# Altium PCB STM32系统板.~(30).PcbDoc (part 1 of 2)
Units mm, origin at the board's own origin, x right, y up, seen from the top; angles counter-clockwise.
Board outline 191.7 x 146.7 mm, 4 copper layers (TopLayer, MidLayer1, MidLayer2, BottomLayer); 154 components, 101 nets, 554 pads, 177 vias.
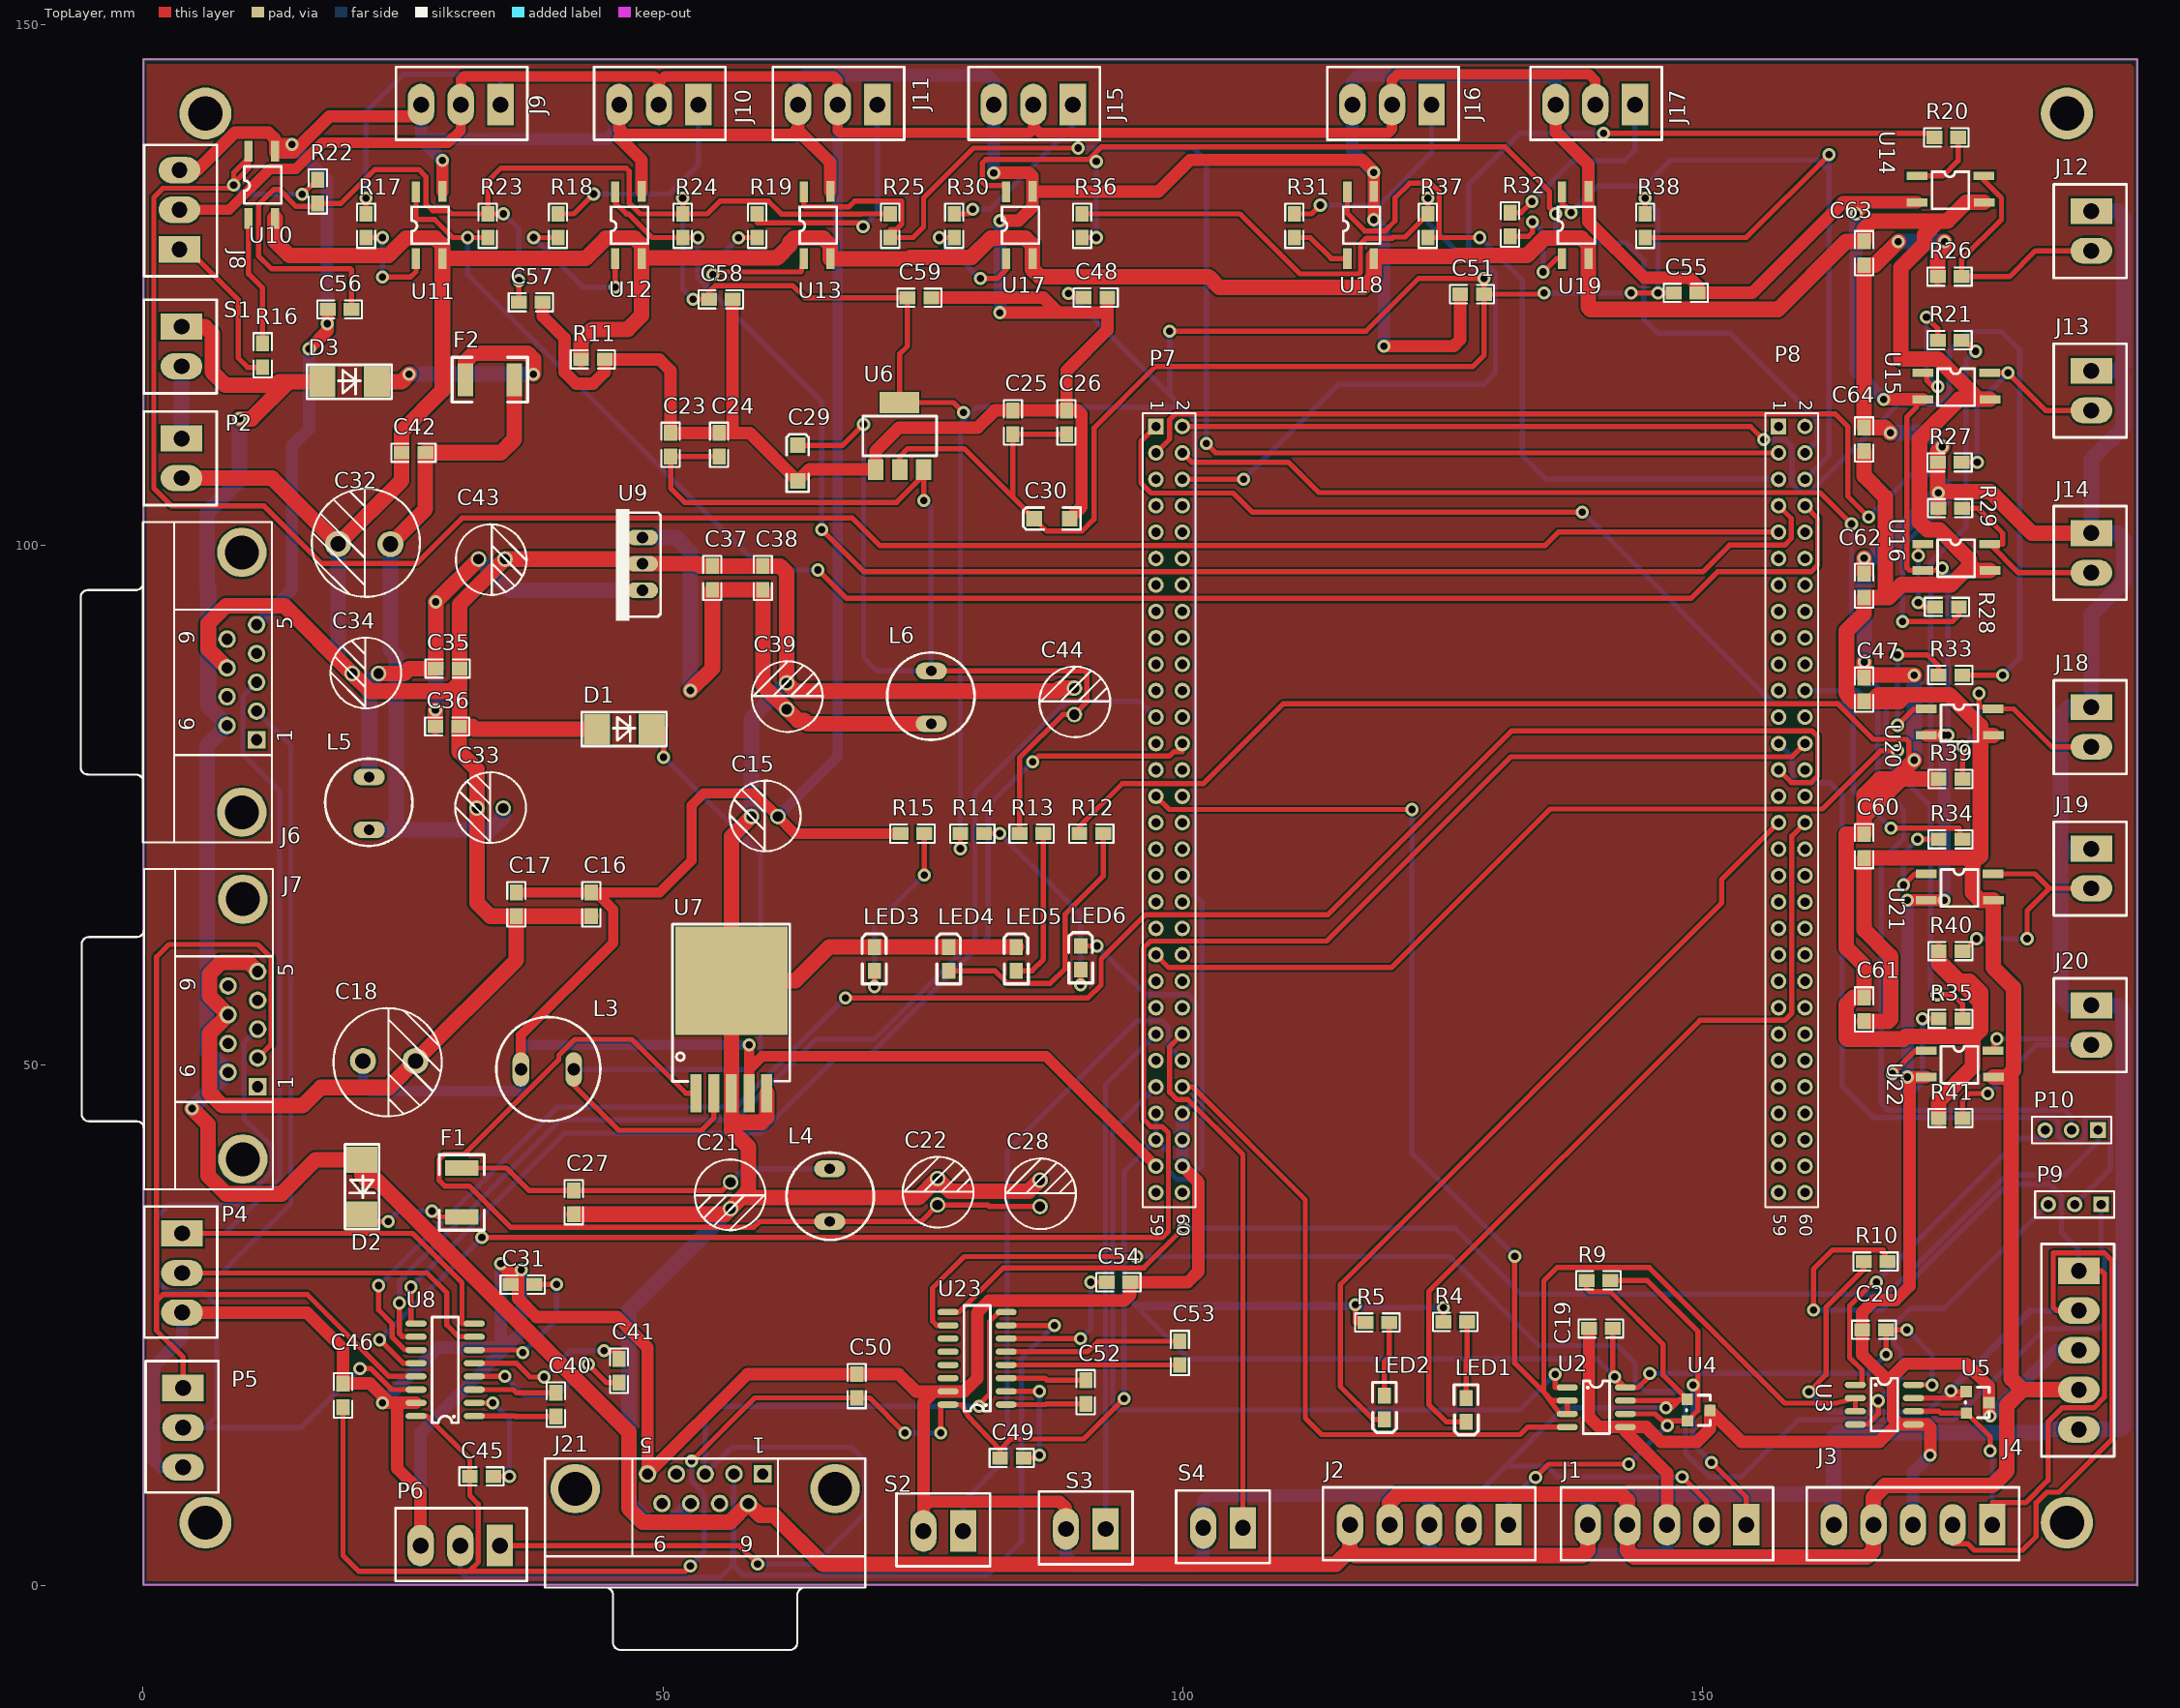
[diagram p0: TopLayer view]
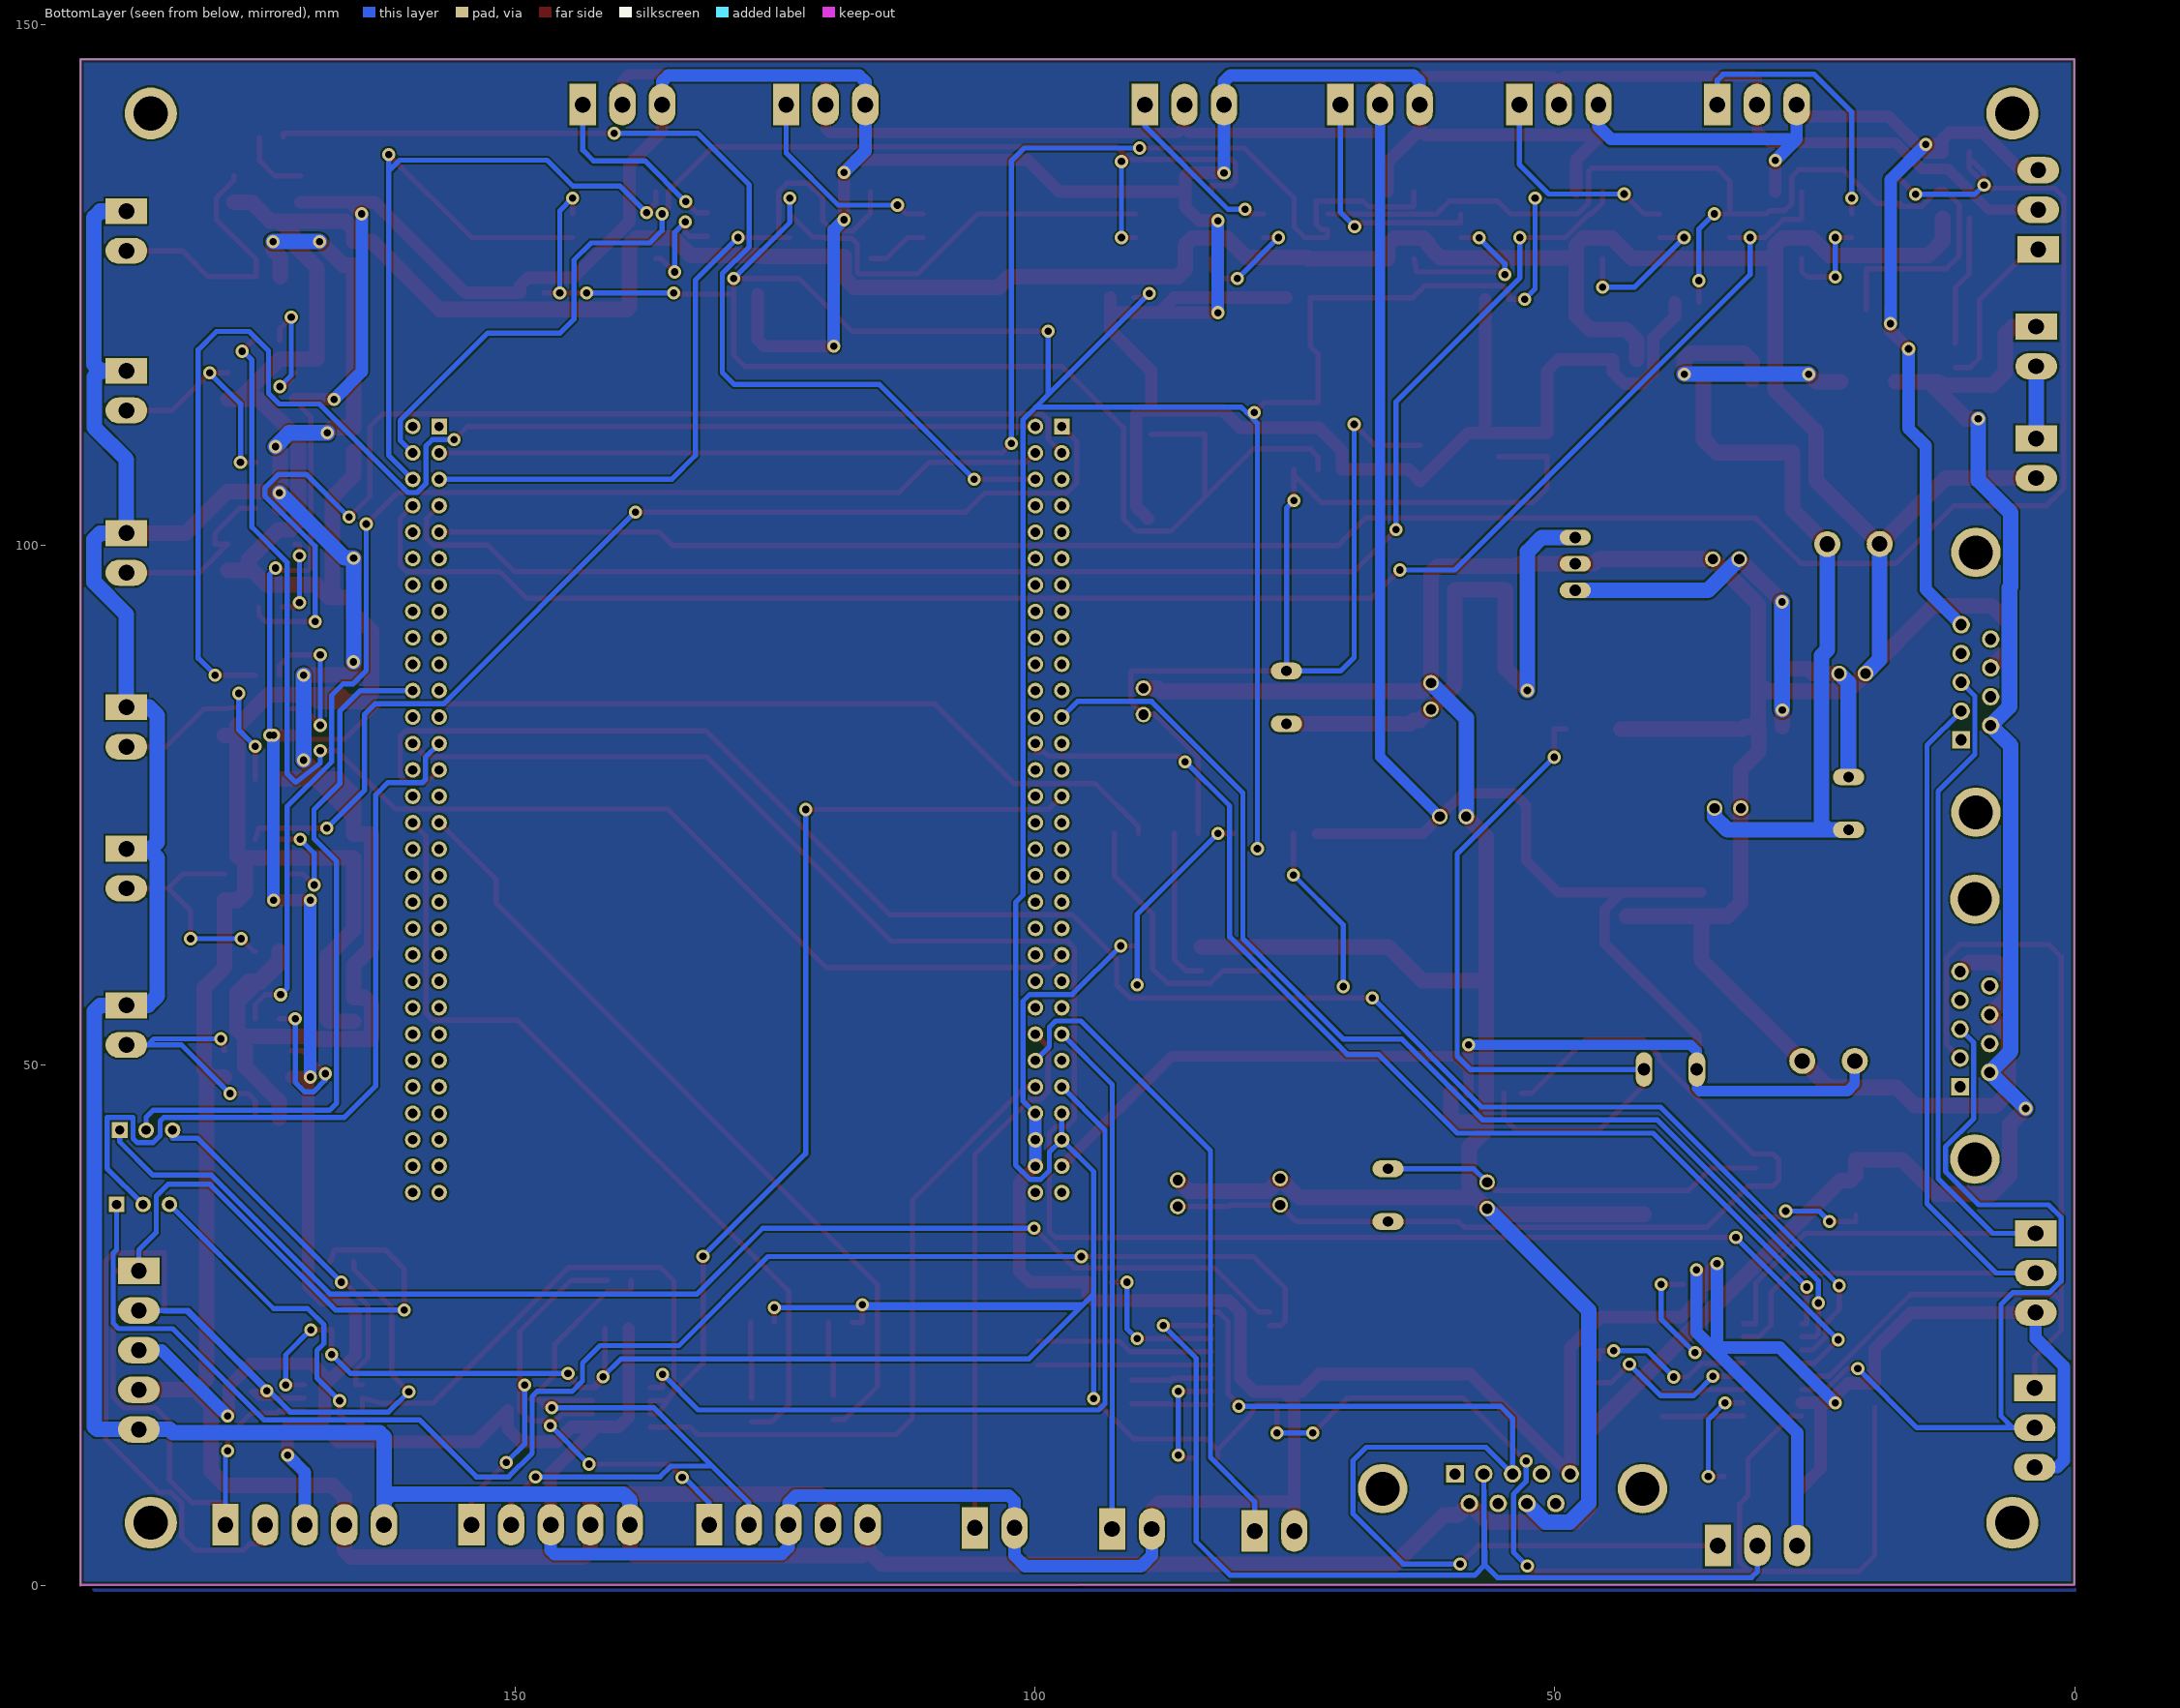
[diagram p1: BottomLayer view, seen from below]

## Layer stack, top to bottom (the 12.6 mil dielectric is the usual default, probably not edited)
TopSolder: solder mask 0.0102, Solder Resist, Dk 3.5
TopLayer: signal copper 0.0356
Dielectric1: dielectric 0.32, FR-4, Dk 4.8
MidLayer1: signal copper 0.0356
Dielectric2: dielectric 0.32, FR-4, Dk 4.8
MidLayer2: signal copper 0.0356
Dielectric3: dielectric 0.32, FR-4, Dk 4.8
BottomLayer: signal copper 0.0356
BottomSolder: solder mask 0.0102, Solder Resist, Dk 3.5

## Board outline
0.05,0.05 0.05,146.7 191.75,146.7 191.75,0

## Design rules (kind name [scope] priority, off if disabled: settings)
Clearance [All] p1: gap=0.2 ignorepadtopadclearanceinfootprint=FALSE except(0: Arc-Hole Track-Hole SMDPad-Hole THPad-Hole Via-Hole Fill-Hole Poly-Hole Region-Hole Text-Hole)
FabricationTestPointUsage TestPointUsage [All] p1: valid=0 allowmultiple=FALSE
FabricationTestpoint Testpoint [All] p1: side=3 testpointundercomponent=TRUE minsize=1.016 maxsize=2.54 preferedsize=1.524 minholesize=0.508 maxholesize=1.016 preferedholesize=0.813 testpointgrid=0.025 allowsidetop=TRUE allowsidebottom=TRUE usegrid=TRUE gridtolerance=0
HoleSize [All] p1: absolutevalues=TRUE maxlimit=5.5 minlimit=0.025 maxpercent=80.000 minpercent=20.000
PlaneConnect [All] p1: planeconnectstyle=Relief reliefexpansion=1 reliefentries=4 reliefconductorwidth=2 reliefairgap=0.254
PolygonConnect [All] p1: connectstyle=Relief reliefconductorwidth=0.3 reliefentries=4 polygonreliefangle="90 Angle" airgapwidth=0.254
RoutingCorners [All] p1: cornerstyle=45-Degree minsetback=0.025 maxsetback=4
RoutingLayers [All] p1: top layer_v5=TRUE mid layer 1_v5=FALSE mid layer 2_v5=FALSE bottom layer_v5=TRUE
RoutingVias [All] p1: holewidth=0.711 width=1.27 viastyle="Through Hole" minholewidth=0.711 minwidth=1.27 maxholewidth=0.711 maxwidth=1.27
SilkToSolderMaskClearance SilkscreenOverComponentPads [IsPad] p1: minsilkscreentomaskgap=0.254 clearancetoexposedcopper=TRUE
SolderMaskExpansion [All] p1: expansion=0.2
Width [All] p1: maxlimit=10 minlimit=0.254 preferedwidth=0.5 midlayer1_maxwidth=0.762 midlayer1_prefwidth=0.381 midlayer2_maxwidth=0.762 midlayer2_prefwidth=0.381 minimp=50.000000 maximp=50.000000 favimp=50.000000
23 further rules are at their usual default settings.

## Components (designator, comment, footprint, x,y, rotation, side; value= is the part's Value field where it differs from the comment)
C15 "100uf/16V" C6.5-35V47uf 61.05,73.9 r180 top
C16 "10nf/50V 5%" 0805C 43.082,66.55 r270 top
C17 "100nf/50V 5%" 0805C 35.882,66.55 r270 top
C18 "470u/16V" C10-35V330uf 21.15,50.4 r0 top
C19 "100nf/50V 5%" 0805C 139.1,24.65 r0 top
C20 "100nf/50V 5%" 0805C 165.362,24.532 r0 top
C21 "10uf/35V" C6.5-35V47uf 56.5,38.741 r270 top
C22 "220uf/35V" C6.5-35V47uf 76.4,36.551 r90 top
C23 "100nf/50V 5%" 0805C 50.75,108.55 r90 top
C24 "10nf/50V 5%" 0805C 55.418,108.55 r90 top
C25 "100nf/50V 5%" 0805C 83.668,110.7 r90 top
C26 "10nf/50V 5%" 0805C 88.818,110.7 r90 top
C27 "100nf/50V 5%" 0805C 41.4,37.9 r270 top
C28 "10u/35V" C6.5-35V47uf 86.25,36.401 r90 top
C29 "16V10uf" 1206-2 62.95,107.885 r90 top
C30 "16V10uf" 1206-2 87.4,102.55 r180 top
C31 "100nf/50V 5%" 0805C 37.588,28.918 r180 top
C32 "220uf/35V" C10-35V330uf 23.794,100.091 r180 top
C33 "10uf/35V" C6.5-35V47uf 34.64,74.7 r180 top
C34 "220uf/35V" C6.5-35V47uf 22.65,87.65 r180 top
C35 "100nf/50V 5%" 0805C 28.2,88.1 r0 top
C36 "10nf/50V 5%" 0805C 28.162,82.532 r0 top
C37 "10nf/50V 5%" 0805C 54.768,95.75 r90 top
C38 "100nf/50V 5%" 0805C 59.618,95.75 r90 top
C39 "47uf 50V" C6.5-35V47uf 61.9,84.21 r90 top
C40 "100nf/50V 5%" 0805C 39.718,16.262 r90 top
C41 "100nf/50V 5%" 0805C 45.75,21.7 r270 top
C42 "100nf/50V 5%" 0805C 27.1,108.9 r180 top
C43 "47uf 50V" C6.5-35V47uf 32.26,98.65 r0 top
C44 "10uf 50V" C6.5-35V47uf 89.55,83.7 r90 top
C45 "100nf/50V 5%" 0805C 31.462,10.432 r0 top
C46 "10uf/50V 5%" 0805C 19.25,17.15 r90 top
C47 "100nf/50V 5%" 0805C 165.518,85.012 r90 top
C48 "100nf/50V 5%" 0805C 92.688,123.818 r180 top
C49 "100nf/50V 5%" 0805C 82.45,12.2 r0 top
C50 "10uf/50V 5%" 0805C 68.65,18.05 r90 top
C51 "100nf/50V 5%" 0805C 126.7,124.1 r0 top
C52 "100nf/50V 5%" 0805C 90.668,17.457 r90 top
C53 "100nf/50V 5%" 0805C 99.682,23.402 r270 top
C54 "100nf/50V 5%" 0805C 92.7,29.1 r0 top
C55 "100nf/50V 5%" 0805C 149.438,124.268 r180 top
C56 "100nf/50V 5%" 0805C 17.812,122.632 r0 top
C57 "100nf/50V 5%" 0805C 38.388,123.368 r180 top
C58 "100nf/50V 5%" 0805C 56.65,123.65 r180 top
C59 "100nf/50V 5%" 0805C 75.75,123.8 r180 top
C60 "100nf/50V 5%" 0805C 165.518,69.962 r90 top
C61 "100nf/50V 5%" 0805C 165.518,54.262 r90 top
C62 "100nf/50V 5%" 0805C 165.518,95.002 r90 top
C63 "100nf/50V 5%" 0805C 165.472,129.152 r270 top
C64 "100nf/50V 5%" 0805C 165.518,109.062 r90 top
D1 "1N5822" SS34 48.4,82.75 r90 top
D2 "1N5822" SS34 21.49,36.157 r0 top
D3 "1N5822" SS34 21.984,116.14 r90 top
F1 "500mA" 1812 30.65,37.751 r90 top
F2 "500mA" 1812 33.35,115.9 r0 top
J1 "Header 5" CON-5P-3.81 154.119,5.8 r180 top
J2 "Header 5" CON-5P-3.81 131.249,5.8 r180 top
J3 "Header 5" CON-5P-3.81 177.769,5.8 r180 top
J4 "Header 5" CON-5P-3.81 186.15,30.159 r270 top
J6 "母头" DSUB1.385-2H9 0,86.805 r90 top
J7 "公头" DSUB1.385-2H9 0.1,53.455 r90 top
J8 "CON3" CON-3P-3.81 3.525,128.455 r90 top
J9 "CON3" CON-3P-3.81 34.335,142.375 r180 top
J10 "CON3" CON-3P-3.81 53.385,142.375 r180 top
J11 "CON3" CON-3P-3.81 70.585,142.375 r180 top
J12 "红色" CON-2P-3.81 187.35,132.1 r270 top
J13 "红色" CON-2P-3.81 187.35,116.75 r270 top
J14 "红色" CON-2P-3.81 187.35,101.15 r270 top
J15 "CON3" CON-3P-3.81 89.395,142.375 r180 top
J16 "CON3" CON-3P-3.81 123.885,142.375 r180 top
J17 "CON3" CON-3P-3.81 143.435,142.375 r180 top
J18 "红色" CON-2P-3.81 187.35,84.41 r270 top
J19 "红色" CON-2P-3.81 187.35,70.8 r270 top
J20 "红色" CON-2P-3.81 187.35,55.75 r270 top
J21 "母头" DSUB1.385-2H9 54.055,-0.23 r180 top
L3 "331" LC-10 38.45,49.85 r0 top
L4 "Inductor" LC-8.2 66.05,40.001 r270 top value="10uH 2A"
L5 "Inductor" LC-8.2 21.733,72.654 r90 top value="10uH 2A"
L6 "10uH 2A" LC-8.2 75.783,82.854 r90 top
LED1 "LED R" 0805D 127.2,17.916 r270 top
LED2 "LED B" 0805D 119.35,18.15 r270 top
LED3 "LED G" 0805D 70.35,59.15 r90 top
LED4 "LED B" 0805D 77.5,59.15 r90 top
LED5 "LED R" 0805D 84,59.15 r90 top
LED6 "LED B" 0805D 90.2,59.25 r90 top
P2 "Power_24V" CON-2P-3.81 3.7,110.25 r270 top
P4 "RS232_2" CON-3P-3.81 3.725,33.795 r270 top
P5 "RS232_4" CON-3P-3.81 3.825,18.925 r270 top
P6 "RS232_1" CON-3P-3.81 34.285,3.825 r180 top
P7 "Header 30X2" HDR2X30 97.4,111.4 r270 top
P8 "Header 30X2" HDR2X30 157.276,111.4 r270 top
P9 "TX5" HDR1X3 188.29,36.6 r180 top
P10 "RX5" HDR1X3 187.99,43.75 r180 top
R4 "10K 1%" 0805R 127.3,25.35 r180 top
R5 "10K 1%" 0805R 119.813,25.293 r180 top
R9 "120R 1%" 0805R 138.837,29.257 r0 top
R10 "120R 1%" 0805R 165.487,31.057 r0 top
R11 "0R 1%" 0805R 42.137,117.807 r0 top
R12 "47K 1%" 0805R 92.302,72.302 r180 top
R13 "10k 1%" 0805R 86.552,72.302 r180 top
R14 "10K 1%" 0805R 80.852,72.302 r180 top
R15 "10K 1%" 0805R 75.102,72.302 r180 top
R16 "620R 1%" 0805R 11.457,119.363 r270 top
R17 "620R 1%" 0805R 21.493,129.587 r90 top
R18 "620R 1%" 0805R 39.95,129.587 r90 top
R19 "620R 1%" 0805R 59.1,129.587 r90 top
R20 "620R 1%" 0805R 174.513,139.243 r180 top
R21 "620R 1%" 0805R 172.6,119.65 r0 top
R22 "2K 1%" 0805R 16.757,135.113 r270 top
R23 "2K 1%" 0805R 33.193,129.587 r90 top
R24 "2K 1%" 0805R 51.943,129.587 r90 top
R25 "2K 1%" 0805R 71.893,129.587 r90 top
R26 "2K 1%" 0805R 172.6,125.764 r0 top
R27 "2K 1%" 0805R 172.6,107.9 r0 top
R28 "620R 1%" 0805R 172.35,94 r0 top
R29 "2K 1%" 0805R 172.65,103.5 r0 top
R30 "620R 1%" 0805R 78.05,129.587 r90 top
R31 "620R 1%" 0805R 110.75,129.587 r90 top
R32 "620R 1%" 0805R 131.493,129.705 r90 top
R33 "620R 1%" 0805R 172.673,87.457 r0 top
R34 "620R 1%" 0805R 172.687,71.657 r0 top
R35 "620R 1%" 0805R 172.687,54.4 r0 top
R36 "2K 1%" 0805R 90.343,129.587 r90 top
R37 "2K 1%" 0805R 123.593,129.587 r90 top
R38 "2K 1%" 0805R 144.493,129.587 r90 top
R39 "2K 1%" 0805R 172.687,77.457 r0 top
R40 "2K 1%" 0805R 172.687,60.907 r0 top
R41 "2K 1%" 0805R 172.687,44.857 r0 top
S1 "SW POWER" CON-2P-3.81 3.7,121 r270 top
S2 "KEY-9" CON-2P-3.81 78.86,5.2 r180 top
S3 "KEY-9" CON-2P-3.81 92.56,5.4 r180 top
S4 "KEY-9" CON-2P-3.81 105.76,5.5 r180 top
U2 "SP3485" SO-8 139.75,17.1 r0 top
U3 "SP3485" SO-8 167.45,17.35 r0 top
U4 "SM712" SM712 147.757,18.918 r270 top
U5 "SM712" SM712 174.577,19.668 r270 top
U6 "LM1117-3.3" SOT-223 73.123,110.226 r0 top
U7 "LM2596-5" TO-263-5 56.6,57.65 r0 top
U8 "MAX3232" SO-16 29.05,20.7 r180 top
U9 "ZLG K7805-500" TO-220 48.05,99 r90 top
U10 "TLP181" TLP-181 10.15,131.42 r90 top
U11 "TLP181" TLP-181 26.25,127.548 r90 top
U12 "TLP181" TLP-181 45.41,127.548 r90 top
U13 "TLP181" TLP-181 63.55,127.548 r90 top
U14 "TLP181" TLP-181 170.6,135.49 r0 top
U15 "TLP181" TLP-181 171.15,116.55 r0 top
U16 "TLP181" TLP-181 171.15,100.1 r0 top
U17 "TLP181" TLP-181 83,127.548 r90 top
U18 "TLP181" TLP-181 115.81,127.548 r90 top
U19 "TLP181" TLP-181 136.45,127.548 r90 top
U20 "TLP181" TLP-181 171.474,84.25 r0 top
U21 "TLP181" TLP-181 171.474,68.39 r0 top
U22 "TLP181" TLP-181 171.474,51.39 r0 top
U23 "MAX3232" SO-16 80.2,21.8 r180 top

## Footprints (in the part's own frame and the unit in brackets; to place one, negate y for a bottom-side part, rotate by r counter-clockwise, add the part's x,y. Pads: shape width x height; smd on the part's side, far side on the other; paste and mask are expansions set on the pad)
0805C [mil]
  rect 60x50 smd: 1(-1.89,0.71) 2(88.11,0.71)
  silkscreen extent -41,-34 127,35
0805D [mil]
  rect 60x50 smd: 1(-3.11,0.95) 2(86.89,0.95)
  silkscreen extent -53,-44 137,47
0805R [mil]
  rect 60x50 smd: 1(-0.91,1.69) 2(89.09,1.69)
  silkscreen extent -40,-33 128,36
1206-2 [mm]
  rect 1.5x1.5 smd: 1(1.715,0) 2(-1.714,0)
  silkscreen extent -2.76,-1.05 2.76,1.05
1812 [mil]
  rect 60x125 smd: 1(-92.5,0) 2(92.5,0)
  silkscreen extent -143,-85 142,85
C6.5-35V47uf [mm]
  round 1.5 hole 1: 1(0,0) 2(2.54,0)
  silkscreen extent -2.18,-3.45 4.62,3.35
C10-35V330uf [mm]
  round 2.5 hole 1.5: 1(0,0) 2(5.044,-0.009)
  silkscreen extent -2.83,-5.33 7.57,5.07
CON-2P-3.81 [mm]
  rect 2.5x4 hole 1.524: 1(0,0)
  oval 2.5x4 hole 1.524: 2(3.81,0)
  silkscreen extent -2.59,-3.61 6.41,3.39
CON-3P-3.81 [mil]
  rect 100x157.48 hole 60: 1(-1,1)
  oval 100x157.48 hole 60: 2(149,1) 3(299,1)
  silkscreen extent -103,-141 394,135
CON-5P-3.81 [mm]
  rect 2.54x4 hole 1.524: 1(-0.051,0)
  oval 2.54x4 hole 1.524: 2(3.759,0) 3(7.569,0) 4(11.379,0) 5(15.189,0)
  silkscreen extent -2.64,-3.61 17.78,3.39
DSUB1.385-2H9 [mm] "Connector; D Subminiature; 9 Position; Right Angle; Pitch 1.385 mm"
  rect 1.69x1.69 hole 1.09: 1(-5.54,-10.92)
  round 1.69 hole 1.09: 2(-2.77,-10.92) 3(0,-10.92) 4(2.77,-10.92) 5(5.54,-10.92) 6(-4.155,-8.08) 7(-1.385,-8.08) 8(1.385,-8.08) 9(4.155,-8.08)
  round 4.76 hole 3.26: 10(-12.495,-9.5) 11(12.495,-9.5)
  silkscreen extent -15.4,-12.4 15.4,6
HDR1X3 [mm] "Connector; Header; 3 Position"
  rect 1.5x1.5 hole 0.9: 1(0,0)
  round 1.5 hole 0.9: 2(2.54,0) 3(5.08,0)
  silkscreen extent -1.27,-1.27 6.35,1.27
HDR2X30 [mm] "Connector; Header; 30x2 Position"
  rect 1.5x1.5 hole 0.9: 1(0,0)
  round 1.5 hole 0.9: 2(0,2.54) 3(2.54,0) 4(2.54,2.54) 5(5.08,0) 6(5.08,2.54) 7(7.62,0) 8(7.62,2.54) 9(10.16,0) 10(10.16,2.54) 11(12.7,0) 12(12.7,2.54) 13(15.24,0) 14(15.24,2.54) 15(17.78,0) 16(17.78,2.54) 17(20.32,0) 18(20.32,2.54) 19(22.86,0) 20(22.86,2.54) 21(25.4,0) 22(25.4,2.54) 23(27.94,0) 24(27.94,2.54) 25(30.48,0) 26(30.48,2.54) 27(33.02,0) 28(33.02,2.54) 29(35.56,0) 30(35.56,2.54) 31(38.1,0) 32(38.1,2.54) 33(40.64,0) 34(40.64,2.54) 35(43.18,0) 36(43.18,2.54) 37(45.72,0) 38(45.72,2.54) 39(48.26,0) 40(48.26,2.54) 41(50.8,0) 42(50.8,2.54) 43(53.34,0) 44(53.34,2.54) 45(55.88,0) 46(55.88,2.54) 47(58.42,0) 48(58.42,2.54) 49(60.96,0) 50(60.96,2.54) 51(63.5,0) 52(63.5,2.54) 53(66.04,0) 54(66.04,2.54) 55(68.58,0) 56(68.58,2.54) 57(71.12,0) 58(71.12,2.54) 59(73.66,0) 60(73.66,2.54)
  silkscreen extent -1.27,-1.27 75.06,3.81
LC-8.2 [mm]
  oval 1.6x3 hole 1: 1(-0.034,-0.017) 2(5.046,-0.017)
  silkscreen extent -1.58,-4.17 6.81,4.23
LC-10 [mm]
  oval 1.6x3.3 hole 1.2: 1(-2.117,-0.271) 2(2.963,-0.271)
  silkscreen extent -4.47,-5.23 5.53,4.77
SM712 [mm]
  rect 1.1x1.1 smd: 1(1.068,0.743) 2(3.128,0.763) 3(2.118,2.923)
  silkscreen extent 0.65,0.66 3.57,2.95
SO-8 [mil]
  oval 80x24 smd: 1(-110,75) 2(-110,25) 3(-110,-25) 4(-110,-75) 5(110,-75) 6(110,-25) 7(110,25) 8(110,75)
  silkscreen extent -50,-100 50,100
SO-16 [mil]
  oval 80x24 smd: 1(-110,175) 2(-110,125) 3(-110,75) 4(-110,25) 5(-110,-25) 6(-110,-75) 7(-110,-125) 8(-110,-175) 9(110,-175) 10(110,-125) 11(110,-75) 12(110,-25) 13(110,25) 14(110,75) 15(110,125) 16(110,175)
  silkscreen extent -50,-200 50,200
SOT-223 [mil]
  rect 59x79 smd: 1(-104.55,-116.77) 2(-14,-116.77) 3(76.55,-116.77)
  rect 150x79 smd: 2(-14.67,136.77)
  silkscreen extent -154,-65 126,85
SS34 [mm]
  rect 3x2.5 smd: 1(-0.44,4.743) 2(-0.44,-0.517)
  silkscreen extent -2.08,-1.93 1.19,6.22
TLP-181 [mm]
  rect 2x0.8 smd: 1(0,0) 2(0,-2.54) 3(6.452,-2.54) 4(6.426,0)
  silkscreen extent 1.42,-3.15 4.98,0.41
TO-220 [mm]
  oval 1.5x3 hole 1.1: 1(-3.35,0.025) 2(-0.805,0.029) 3(1.735,0.029)
  silkscreen extent -6.27,-1.72 4.45,2.6
TO-263-5 [mm]
  rect 1.07x3.66 smd: 1(-3.425,-10.36) 2(-1.725,-10.36) 3(-0.025,-10.36) 4(1.675,-10.36) 5(3.375,-10.36)
  rect 10.8x10.41 smd: 3(-0.025,0.465)
  silkscreen extent -5.68,-9.21 5.6,5.89

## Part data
C15 C18 C21 C22 C28 C32 C33 C34 C39 C43 C44: library part "CAPACITOR POL", "Capacitor"
C16 C17 C19 C20 C23 C24 C25 C26 C27 C31 C35 C36 C37 C38 C40 C41 C42 C45 C46 C47 C48 C49 C50 C51 C52 C53 C54 C55 C56 C57 C58 C59 C60 C61 C62 C63 C64: library part CAP, "Capacitor"
C29 C30: library part CAP+
D1 D2 D3: library part DIODE, "Diode"
F1 F2: library part "Fuse 1", "Fuse"
J1 J2 J3 J4: "Header, 5-Pin"
J6 J7 J21: library part "D Connector 9", "Receptacle Assembly, 9 Position, Right Angle", PackageDocument=O
J8 J9 J10 J11 J15 J16 J17: "Connector"
J12 J13 J14 J18 J19 J20 P2: library part CON2, "Connector"
L3: library part INDUCTOR
L6: library part INDUCTOR1
LED1 LED2 LED3 LED4 LED5 LED6: library part LED
P4 P5 P6 P9 P10: library part "Header 3", "Header, 3-Pin"
P7 P8: "Header, 30-Pin, Dual row"
R4 R5 R9 R10 R11 R12 R13 R14 R15 R16 R17 R18 R19 R20 R21 R22 R23 R24 R25 R26 R27 R28 R29 R30 R31 R32 R33 R34 R35 R36 R37 R38 R39 R40 R41: library part RES2
S1: library part "SW SPST"
S2 S3 S4: library part KEY-2
U2 U3: library part MAX485
U6: library part LM1117
U7: library part LM2596-5.0
U9: library part VOLTREG
U10 U11 U12 U13 U14 U15 U16 U17 U18 U19 U20 U21 U22: library part TLP521-1

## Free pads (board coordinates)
  round 5 hole 3.3: 23(185,141.5) 24(6,141.5) 25(6,6) 26(185,6)

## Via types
v1: diameter 1.27, hole 0.711, TopLayer to BottomLayer, 177 vias

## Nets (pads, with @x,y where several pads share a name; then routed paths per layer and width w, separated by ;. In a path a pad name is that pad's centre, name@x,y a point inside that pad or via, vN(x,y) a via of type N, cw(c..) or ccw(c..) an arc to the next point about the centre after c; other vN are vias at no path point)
3V3: C19.2 C20.2 C25.1 C26.1 C30.1 C45.1 C46.1 C48.2 C49.1 C50.1 C51.2 C55.2 C56.2 C57.2 C58.2 C59.2 P7.53 P7.55 R4.2 R5.2 R14.2 R22.2 R23.2 R24.2 R25.2 R36.2 R37.2 R38.2 U2.8 U3.8 U6.2 U8.16 U23.16 | length 841.1
  TopLayer w0.5: C46.1@19.232,17.102 19.232,2.835 20.725,1.341 31.368,1.341 ; C56.2@20.05,122.65 20.05,126.462 19.948,126.563 12.343,126.563 11.099,127.808 11.099,132.71 12.597,134.209 13.08,134.209 14.731,132.558 16.8,132.558 R22.2@16.8,132.85 19.024,132.85 22.287,136.114 26.517,136.114 27.202,135.428 27.202,132.812 27.863,132.151 29.347,132.151 29.648,131.85 R23.2@33.15,131.85 ; U8.16@26.256,16.255 27.304,16.255 31.414,12.145 C45.1@31.414,10.45 31.414,8.606 32.232,7.788 32.232,2.205 31.368,1.341 ; v1(34.667,131.85) R23.2@33.15,131.85 ; C57.2@36.15,123.35 v1(36.15,125.421) ; v1(51.891,133.371) 51.9,133.362 R24.2@51.9,131.85 ; v1(52.628,1.824) 52.145,1.341 31.368,1.341 ; v1(52.755,11.933) 58.824,18.002 C50.1@68.632,18.002 69.874,18.002 v1(73.251,14.626) ; v1(52.888,123.632) C58.2@54.412,123.632 54.412,124.309 55.023,124.92 62.501,124.92 63.639,123.782 C59.2@73.512,123.782 73.512,119.121 72.75,118.359 U6.2@72.75,113.7 77.937,113.7 v1(78.891,112.746) ; R25.2@71.85,131.85 69.025,131.85 69.011,131.835 61.377,131.835 60.146,133.066 55.469,133.066 54.253,131.85 R24.2@51.9,131.85 ; U6.2@72.767,107.26 72.767,108.504 73.529,109.266 78.969,109.266 83.65,104.585 ; v1(76.707,14.626) 76.707,17.355 U23.16@77.406,17.355 78.702,17.355 79.304,16.291 82.402,13 ; v1(78.589,70.81) R14.2@78.589,72.259 ; C49.1@82.402,12.218 82.402,13 ; C26.1@88.8,110.652 C25.1@83.65,110.652 83.65,104.585 ; v1(88.975,124.201) 89.376,123.8 C48.2@90.45,123.8 ; R36.2@90.3,131.85 105.482,131.85 111.251,126.081 116.915,126.081 117.068,126.233 117.068,128.951 117.619,129.503 120.135,129.503 120.135,129.611 121.36,129.611 123.55,131.801 R37.2@123.55,131.85 v1(123.55,133.371) ; v1(94.335,17.928) 90.454,14.047 83.449,14.047 82.402,13 ; v1(98.729,120.569) 117.601,120.569 122.674,125.642 v1(128.938,125.642) C51.2@128.938,124.118 ; v1(116.585,26.945) 116.585,25.25 R5.2@117.55,25.25 ; R4.2@125.037,25.307 v1(125.037,26.665) ; v1(134.721,124.252) 134.587,124.118 C51.2@128.938,124.118 ; C19.2@141.338,24.668 141.338,19.892 142.225,19.005 U2.8@142.544,19.005 ; v1(141.513,20.036) U2.8@142.544,19.005 ; v1(143.103,124.252) 143.105,124.25 v1(145.676,124.25) C55.2@147.2,124.25 ; v1(144.449,133.371) v1(144.449,133.371) R38.2@144.45,131.85 ; v1(144.881,20.341) 144.881,20.112 143.774,19.005 U2.8@142.544,19.005 ; v1(167.6,22.156) C20.2@167.6,24.55 v1(169.62,24.55) ; U3.8@170.244,19.255 172.027,19.255 v1(172.033,19.248) ; R23.2@33.15,131.85 33.15,134.975 34.416,136.241 46.456,136.241 46.76,135.936 46.76,132.888 47.798,131.85 R24.2@51.9,131.85 ; 83.65,104.585 C30.1@85.685,102.55 86.885,101.35 90.314,101.35 91.439,102.474 91.439,111.25 97.367,117.178 127.888,117.178 128.938,118.228 C51.2@128.938,124.118
  BottomLayer w0.5: v1(34.667,131.85) 36.15,130.367 v1(36.15,125.421) ; v1(51.891,133.371) 51.891,124.629 v1(52.888,123.632) ; v1(52.628,1.824) 53.974,3.17 53.974,8.733 52.755,9.952 v1(52.755,11.933) ; v1(73.251,14.626) v1(76.707,14.626) ; v1(78.589,70.81) 78.589,111.707 79.628,112.745 ; v1(78.891,112.746) 79.628,112.745 ; v1(88.975,124.201) 98.729,114.448 ; v1(94.335,17.928) 94.335,27.986 ; P7.53@97.4,45.36 P7.55@97.4,42.82 ; v1(98.729,120.569) 98.729,114.448 ; v1(116.585,26.945) 95.655,26.945 ; v1(123.55,133.371) 123.55,131.03 v1(128.938,125.642) ; v1(125.037,26.665) 95.655,26.665 ; v1(134.721,124.252) v1(143.103,124.252) ; v1(141.513,20.036) 139.786,21.763 100.558,21.763 95.655,26.665 ; v1(144.449,133.371) 145.676,132.143 v1(145.676,124.25) ; v1(144.881,20.341) 165.785,20.341 v1(167.6,22.156) ; v1(169.62,24.55) 172.033,22.137 v1(172.033,19.248) ; 79.628,112.745 80.136,113.254 99.923,113.254 ; 94.335,27.986 94.335,39.755 P7.55@97.4,42.82 ; 94.335,27.986 95.376,26.945 ; 95.376,26.945 95.655,26.665 ; 95.376,26.945 95.655,26.945 ; 95.655,26.665 95.655,26.945 ; P7.55@97.4,42.82 98.602,41.618 98.602,39.848 99.44,39.01 100.456,39.01 101.84,40.394 101.84,65.642 101.142,66.34 101.142,112.035 99.923,113.254 ; 98.729,114.448 99.923,113.254
5V: C15.1 C16.1 C17.1 C18.1 J8.2 J9.2 J10.2 J11.2 J15.2 J16.2 J17.2 L3.1 P7.57 R15.2 U7.4 | length 392.5
  TopLayer w1: J8.2@3.5,132.24 8.279,132.24 12.204,136.165 14.706,136.165 17.22,138.679 29.336,138.679 30.55,139.893 J9.2@30.55,142.35 30.55,144.745 30.86,145.055 49.148,145.055 49.6,144.603 49.6,144.491 ; C17.1@35.9,66.598 C16.1@43.1,66.598 C16.1@43.556,66.598 ; L3.1@36.333,49.579 36.333,52.865 45.211,61.743 45.211,64.943 C16.1@43.556,66.598 ; J10.2@49.6,142.35 49.6,144.491 ; U7.4@58.275,47.29 58.275,49.576 ; v1(58.275,51.938) 58.275,49.576 ; R15.2@72.839,72.259 62.692,72.259 C15.1@61.05,73.9 58.806,76.144 53.923,76.144 52.755,74.976 52.755,69.667 49.685,66.598 C16.1@43.556,66.598 ; J15.2@85.61,142.35 85.61,140.266 ; P7.57@97.4,40.28 86.834,50.846 59.545,50.846 58.275,49.576 ; J17.2@139.65,142.35 139.65,144.672 139.064,145.258 120.633,145.258 120.1,144.724 J16.2@120.1,142.35 120.1,139.984 119.76,139.644 86.232,139.644 85.61,140.266 ; 49.6,144.491 50.164,145.055 66.42,145.055 66.8,144.675 J11.2@66.8,142.35 66.8,139.873 67.029,139.644 85.254,139.644 85.61,140 85.61,140.266
  BottomLayer w1: C18.1@21.15,50.4 21.15,48.186 21.831,47.505 36.041,47.505 36.333,47.798 L3.1@36.333,49.579 36.333,51.315 36.956,51.938 v1(58.275,51.938) ; C15.1@61.05,73.9 66.8,79.65 J11.2@66.8,142.35
24V: C47.2 C60.2 C61.2 C62.2 C63.2 C64.2 D2.1 D3.1 J1.5 J2.5 J3.5 J4.5 J6.6 J7.6 J12.1 J13.1 J14.1 J18.1 J19.1 J20.1 J21.6 R12.2 R26.1 R27.1 R29.1 R39.1 R40.1 R41.1 S1.1 | length 741.4
  TopLayer w0.5: R12.2@90.039,72.259 90.039,72.944 94.154,77.059 101.955,77.059 109.625,84.73 162.965,84.73 166.369,81.326 169.544,81.326 169.798,81.072 169.798,78.811 169.798,77.496 165.5,73.198 C60.2@165.5,72.2
  TopLayer w1.5: S1.1@3.7,121 5.968,121 6.654,120.314 6.654,116.632 7.898,115.387 12.767,115.387 13.08,115.7 13.994,115.7 ; v1(4.71,45.83) 6.247,44.293 6.247,39.365 8,37.613 13.309,37.613 16.596,40.9 D2.1@21.05,40.9 21.05,39.416 21.558,38.908 22.529,38.908 46.71,14.727 46.71,7.387 48.056,6.04 56.4,6.04 J21.6@58.21,7.85 59.333,6.727 60.679,6.727 65.404,2.002 114.68,2.002 116.06,3.382 ; v1(9.27,112.136) 10.431,112.136 13.994,115.7 ; D3.1@17.24,115.7 13.994,115.7 ; J2.5@116.06,5.8 116.06,3.382 ; J1.5@138.93,5.8 138.93,3.348 138.422,2.84 116.568,2.84 116.06,3.348 116.06,3.382 ; C47.2@165.5,87.25 165.5,88.763 v1(165.505,88.768) 165.505,87.498 v1(170.306,87.498) ; C62.2@165.5,97.24 v1(165.5,98.75) ; v1(168.02,110.79) 167.51,111.3 C64.2@165.5,111.3 165.5,112.812 165.49,112.822 C63.2@165.49,126.914 166.516,126.914 v1(168.782,129.18) ; v1(170.306,79.319) 168.487,77.5 ; R26.1@172.577,125.807 172.577,127.706 173.227,128.356 v1(173.227,129.18) ; R29.1@172.627,103.543 v1(172.627,105.024) ; R41.1@172.664,44.9 172.664,46.549 175.945,49.83 175.945,52.649 176.035,52.74 ; R40.1@172.664,60.95 172.664,60.045 ; R39.1@172.664,77.5 168.487,77.5 ; v1(173.024,109.469) 172.577,109.022 R27.1@172.577,107.943 172.577,105.074 v1(172.627,105.024) ; J14.1@187.35,101.15 181.622,101.15 177.621,105.151 172.754,105.151 v1(172.627,105.024) ; 165.5,74.513 C60.2@165.5,72.2 163.804,72.2 163.778,72.175 163.778,61.285 165.5,59.564 C61.2@165.5,56.5 164.464,56.5 163.778,55.814 163.778,52.624 163.905,52.497 169.276,52.497 169.519,52.74 176.035,52.74 ; 165.5,74.513 168.487,77.5 ; 165.5,74.513 165.5,75.992 167.008,77.5 168.487,77.5 ; 172.664,60.045 172.664,59.736 174.366,58.034 174.675,58.034 ; 172.664,60.045 174.675,58.034 ; 174.675,58.034 175.64,58.034 176.681,56.993 176.681,56.028 ; 174.675,58.034 176.681,56.028 ; 176.035,52.74 176.681,53.386 176.681,56.028
  BottomLayer w1.5: v1(4.71,45.83) J7.6@8.18,49.3 6.146,51.334 6.146,80.716 J6.6@8.08,82.65 6.273,84.457 6.273,95.88 6.146,96.007 6.146,103.094 9.27,106.218 v1(9.27,112.136) ; J1.5@138.93,5.8 138.93,8.116 139.572,8.758 161.924,8.758 162.58,8.102 ; J3.5@162.58,5.8 162.58,8.102 ; v1(165.505,88.768) 165.5,88.774 v1(165.5,98.75) 166.353,98.75 v1(172.627,105.024) ; v1(168.02,110.79) 171.703,110.79 v1(173.024,109.469) ; v1(168.782,129.18) v1(173.227,129.18) ; v1(170.306,79.319) v1(170.306,87.498) ; J19.1@187.35,70.8 185.282,70.8 ; J13.1@187.35,116.75 189.864,116.75 ; J12.1@187.35,132.1 189.864,132.1 190.474,131.49 190.474,117.36 189.864,116.75 ; 162.58,8.102 162.58,14.245 162.986,14.651 182.865,14.651 183.184,14.97 J4.5@186.15,14.97 190.169,14.97 190.423,15.224 190.423,55.191 189.864,55.75 J20.1@187.35,55.75 185.292,55.75 184.378,56.664 184.378,69.896 185.282,70.8 ; 185.282,70.8 184.998,70.8 184.378,71.42 184.378,83.612 185.176,84.41 J18.1@187.35,84.41 187.349,93.315 190.474,96.439 190.474,100.54 189.864,101.15 J14.1@187.35,101.15 187.349,108.225 190.448,111.323 190.448,116.166 189.864,116.75
485_A: J1.1 J2.1 R9.2 U2.6 U4.2 | length 63
  TopLayer w0.5: v1(133.908,10.358) 135.178,11.628 v1(142.874,11.628) ; R9.2@141.1,29.3 144.627,29.3 149.503,24.423 149.503,18.791 ; U2.6@142.544,16.465 145.411,16.465 146.129,15.79 ; v1(146.582,15.337) 146.129,15.79 ; v1(149.046,19.248) 149.503,18.791 ; v1(150.817,11.806) 154.17,8.453 J1.1@154.17,5.8 ; 146.129,15.79 U4.2@148.52,15.79 149.503,16.773 149.503,18.791
  BottomLayer w0.5: J2.1@131.3,5.8 131.3,7.92 133.738,10.358 v1(133.908,10.358) ; v1(142.874,11.628) v1(146.582,15.337) ; v1(149.046,19.248) 149.046,13.577 v1(150.817,11.806)
485_A2: J3.1 J4.1 R10.2 U3.6 U5.2 | length 101.6
  TopLayer w0.5: v1(160.629,26.437) 160.629,30.399 162.432,32.202 167.344,32.202 R10.2@167.75,31.1 ; U3.6@170.244,16.715 172.694,16.715 172.869,16.54 U5.2@175.34,16.54 177.621,14.259 v1(177.621,12.898) ; J3.1@177.82,5.8 177.82,7.92 181.02,7.92 183.184,10.084 183.184,15.692 184.53,17.039 187.578,17.039 188.619,18.08 188.619,29.931 188.34,30.21 J4.1@186.15,30.21
  BottomLayer w0.5: v1(160.629,26.437) 167.233,26.437 179.348,38.552 183.311,38.552 184.479,37.384 184.479,33.904 186.156,32.228 186.156,30.21 J4.1@186.15,30.21 ; v1(177.621,12.898) 177.82,12.7 J3.1@177.82,5.8
485_B: J1.2 J2.2 R9.1 U2.7 U4.1 | length 72
  TopLayer w0.5: R9.1@138.814,29.3 138.814,28.494 139.093,28.215 141.096,28.215 146.18,23.131 146.18,20.17 U4.1@148.5,17.85 147.775,17.85 147.66,17.735 ; U2.7@142.544,17.735 147.66,17.735 ; v1(146.455,17.039) 146.963,17.039 147.66,17.735 ; v1(148.005,10.409) 150.36,8.054 J1.2@150.36,5.8
  BottomLayer w0.5: J2.2@127.49,5.8 127.49,7.92 131.013,11.443 ; v1(146.455,17.039) 136.609,17.039 131.013,11.443 ; v1(148.005,10.409) 136.027,10.409 134.993,11.443 131.013,11.443
485_B2: J3.2 J4.2 R10.1 U3.7 U5.1 | length 122.5
  TopLayer w0.5: v1(160.197,18.588) 161.828,20.22 161.828,26.687 165.464,30.323 R10.1@165.464,31.1 ; U3.7@170.244,17.985 174.705,17.985 U5.1@175.32,18.6 173.926,18.6 v1(173.862,18.664) ; J3.2@174.01,5.8 174.01,3.983 175.462,3.983 176.097,3.348 180.72,3.348 182.05,4.678 182.05,7.92 183.066,8.936 184.251,8.936 189.331,14.016 189.331,31.212 188.594,31.948 183.692,31.948 183.692,26.716 184.008,26.4 J4.2@186.15,26.4
  BottomLayer w0.5: v1(160.197,18.588) 162.146,16.639 171.608,16.639 181.369,26.4 181.484,26.286 ; v1(173.862,18.664) 181.484,26.286 ; 181.484,26.286 181.598,26.4 J4.2@186.15,26.4 181.484,26.286
GND: C15.2 C16.2 C17.2 C18.2 C21.2 C22.2 C27.2 C28.2 C32.2 C33.2 C34.2 C35.2 C36.2 C37.2 C38.2 C39.2 C42.2 C43.2 C44.2 C47.1 C60.1 C61.1 C62.1 C63.1 C64.1 D1.1 J1.4 J2.4 J3.4 J4.4 J6.8 J7.5 J7.8 J21.8 LED3.2 LED4.2 LED5.2 P2.2 R11.1 U7.3 U7.5 U9.2 U10.2 U11.2 U12.2 U13.2 U14.3 U15.3 U16.3 U17.2 U18.2 U19.2 U20.3 U21.3 U22.3 | length 955.1
  TopLayer w1.5: P2.2@3.7,106.44 12.41,106.44 C32.2@18.75,100.1 24.862,106.212 C42.2@24.862,108.882 24.862,110.939 28.79,114.867 U11.2@28.79,127.548 U11.2@28.79,127.554 ; J6.8@8.08,88.19 6.273,89.997 6.273,92.451 8,94.178 13.582,94.178 C34.2@20.11,87.65 21.811,85.949 29.641,85.949 30.438,86.746 ; J7.5@11.02,58.995 10.127,59.888 7.543,59.888 6.374,58.72 6.374,56.646 J7.8@8.18,54.84 6.374,53.034 6.374,47.36 7.638,46.096 15.341,46.096 17.093,47.849 23.652,47.849 C18.2@26.194,50.391 35.9,60.097 C17.2@35.9,64.312 ; U10.2@12.69,131.42 12.69,129.239 14.096,127.833 23.596,127.833 25.272,129.51 28.104,129.51 28.79,128.824 U11.2@28.79,127.554 ; C27.2@41.418,35.662 55.961,35.662 C21.2@56.5,36.201 57.555,37.256 ; R11.1@42.114,117.85 42.114,119.68 43.177,120.743 46.608,120.743 47.95,122.085 U12.2@47.95,127.548 U12.2@47.95,127.605 ; C16.2@43.1,64.312 C17.2@35.9,64.312 ; D1.1@43.657,82.31 31.901,82.31 31.661,82.55 C36.2@30.438,82.55 ; C15.2@58.51,73.9 56.575,71.965 U7.3@56.575,58.115 ; U7.5@59.975,47.29 59.975,45.004 59.467,44.496 57.083,44.496 56.575,45.004 ; LED5.2@83.976,61.357 LED4.2@77.476,61.357 LED3.2@70.326,61.357 65.979,61.357 62.737,58.115 U7.3@56.575,58.115 ; C28.2@86.25,38.941 85.191,37.882 77.61,37.882 C22.2@76.4,39.091 74.565,37.256 57.555,37.256 ; C44.2@89.55,86.24 88.201,86.24 87.91,85.949 62.701,85.949 C39.2@61.9,86.75 61.9,97.326 61.238,97.988 C38.2@59.6,97.988 C37.2@54.75,97.988 53.571,97.988 53.364,98.195 U9.2@48.021,98.195 46.225,98.195 45.77,98.65 C43.2@34.8,98.65 30.438,94.288 C35.2@30.438,88.118 30.438,86.746 ; J2.4@119.87,5.8 119.87,7.92 120.708,8.758 142.112,8.758 142.74,8.13 J1.4@142.74,5.8 142.74,3.348 143.4,2.688 165.73,2.688 166.39,3.348 J3.4@166.39,5.8 166.39,8.449 167.512,9.571 177.824,9.571 179.221,10.968 179.221,17.281 180.72,18.78 ; C61.1@165.5,54.214 167.824,54.214 168.05,54.44 168.05,60.453 165.5,63.003 C60.1@165.5,69.914 176.115,69.914 ; C64.1@165.5,109.014 165.5,106.655 167.533,104.623 167.533,94.954 ; U14.3@177.052,132.95 175.31,132.95 173.521,131.161 172.648,131.161 ; U16.3@177.602,97.56 176.148,97.56 ; U15.3@177.602,114.01 176.484,114.01 ; U22.3@177.925,48.85 179.196,48.85 ; U21.3@177.925,65.85 U21.3@177.901,65.85 ; U20.3@177.925,81.71 176.681,81.71 ; J4.4@186.15,18.78 180.72,18.78 ; U11.2@28.79,127.554 42.544,127.554 44.5,129.51 47.264,129.51 47.95,128.824 U12.2@47.95,127.605 ; C36.2@30.438,82.55 30.438,86.746 ; C36.2@30.438,82.55 C36.2@30.4,82.55 30.4,80.135 32.1,78.435 C33.2@32.1,74.7 32.1,65.612 33.4,64.312 C17.2@35.9,64.312 ; U12.2@47.95,127.605 60.959,127.605 62.178,128.824 62.178,129.078 62.61,129.51 65.404,129.51 66.09,128.824 U13.2@66.09,127.548 66.09,127.529 73.659,127.529 73.786,127.656 79.653,127.656 81.508,129.51 84.854,129.51 85.54,128.824 U17.2@85.54,127.548 85.54,126.493 86.232,125.801 102.463,125.801 103.504,124.76 117.334,124.76 118.35,125.776 U18.2@118.35,127.548 118.35,127.757 126.212,127.757 126.288,127.833 133.07,127.833 134.746,129.51 138.304,129.51 138.99,128.824 U19.2@138.99,127.548 138.99,122.855 139.193,122.652 157.225,122.652 163.773,129.2 C63.1@165.49,129.2 165.49,130.348 166.303,131.161 172.648,131.161 ; 56.575,45.004 56.575,43.775 58.216,42.134 58.216,37.917 57.555,37.256 ; 56.575,45.004 U7.3@56.575,47.29 U7.3@56.575,58.115 ; 166.222,84.964 168.889,84.964 169.544,85.619 ; 166.222,84.964 C47.1@165.5,84.964 164.484,84.964 163.905,85.542 163.905,85.696 163.8,85.801 163.8,91.742 165.5,93.442 C62.1@165.5,94.954 167.533,94.954 ; 166.222,84.964 166.877,85.619 169.544,85.619 ; 167.533,94.954 167.856,94.954 169.087,96.185 173.833,96.185 175.422,97.774 175.637,97.56 176.148,97.56 ; 169.544,85.619 173.684,85.619 176.681,82.621 176.681,81.71 ; 172.648,131.161 171.327,129.84 171.327,128.968 169.027,126.668 169.027,117.902 172.592,117.902 176.484,114.01 ; 176.115,69.914 176.681,70.48 ; 176.115,69.914 175.945,69.744 175.945,66.561 176.656,65.85 U21.3@177.901,65.85 ; 176.115,69.914 176.471,69.914 176.681,70.125 176.681,70.48 ; 176.148,97.56 175.637,98.071 175.637,98.576 172.744,101.468 171.576,101.468 170.827,102.217 170.827,110.213 174.624,114.01 176.484,114.01 ; 176.681,70.48 176.681,81.71 ; U21.3@177.901,65.85 177.901,59.406 179.856,57.45 179.856,49.51 179.196,48.85 ; 179.196,48.85 179.363,48.85 179.653,48.56 179.653,19.847 180.72,18.78
  BottomLayer w1.5: C32.2@18.75,100.1 18.75,89.01 C34.2@20.11,87.65 ; J21.8@52.67,7.85 50.86,6.04 48.589,6.04 46.71,7.92 46.71,26.411 C21.2@56.5,36.201 ; C15.2@58.51,73.9 58.51,83.36 C39.2@61.9,86.75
